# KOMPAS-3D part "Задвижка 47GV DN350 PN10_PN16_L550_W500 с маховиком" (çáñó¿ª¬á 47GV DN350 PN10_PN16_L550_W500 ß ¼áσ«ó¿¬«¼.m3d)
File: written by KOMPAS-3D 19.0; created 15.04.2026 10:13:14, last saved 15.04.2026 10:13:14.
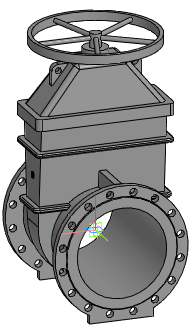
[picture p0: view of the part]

Document properties: Автор: Евгений; Полное имя файла: Z:\3.Личные\kachalov\3d для проектировщиков\2.1 Тип 47GV, 47GV.Z\Задвижка 47GV_DN40-DN600\stp_Задвижка 47GV\Задвижка 47GV DN350 PN10_PN16_L550_W500 с маховиком.m3d

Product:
- Part/product: Задвижка 47GV DN350 PN10_PN16_L550_W500 с маховиком

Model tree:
1. Операция без истории:1  (labels: Задвижка 47GV DN350 PN10_PN16_L550_W500 с маховиком)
